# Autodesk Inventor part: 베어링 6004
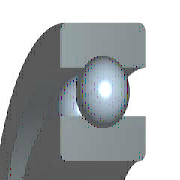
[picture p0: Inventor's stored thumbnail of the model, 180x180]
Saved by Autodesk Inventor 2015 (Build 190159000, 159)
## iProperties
IsCustomPart: 1
Created: 2012-02
Part Number: 베어링 6004
Material: 강철, 연강
Description: 깊은 그루브 볼 베어링
Document SubType Name: Modeling
Standard: KS B 2023
Designer: mduedu
Standards Organization: KS
Language: ko-KR
Size Designation: 6004 - 20 x 42 x 12
Categories: <MemberInstance><Categories><Category DisplayName="샤프트 부품" InternalName="7f7aeb1f-a693-4053-b835-cee3144e0d98" Mnemonic="SHFT"><Category DisplayName="베어링" Inter
Density: 1 g/cm^3
Appearance: 노란색
Author: mduedu
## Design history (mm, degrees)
sketch "스케치" dims "d0" = 5.72 (= -0.26 x WD + 0.26 x BD)
  geometry: L1 (3.14, 15.5)-(8.86, 15.5); L2 (6, 15.5)-(6, 12.64); L3 (6, 15.5)-(6, 18.36); L4 (3.875, 13.586)-(0, 13.586); L5 (0, 10)-(12, 10); L6 (3.875, 17.414)-(0, 17.414); L7 (0, 21)-(12, 21); L8 (12, 10)-(12, 13.586); L9 (8.125, 13.586)-(12, 13.586); L10 (8.125, 17.414)-(12, 17.414); L11 (12, 21)-(12, 17.414); L12 (-1.4, 0)-(8.4, 0) reference; L13 (0, -0.3)-(0, 5.3) reference
  constraints: 22 end point, 4 point on line, 2 collinear, 2 perpendicular, 2 symmetric about line, 1 midpoint, 1 parallel, 14 other
  dimensions: "d9" = 20 diameter of L5 L12 (= WD); "d11" = 42 diameter of L7 L12 (= BD); "d12" = 12 distance between parallel lines of L8 L13 (= KB); "d13" = 27.172 diameter of L9 L12 (= 0.326 x BD + 0.674 x WD)
revolve "본체" stored, may be unused: angle "d6" = 90 deg
revolve "볼" stored, may be unused: angle "d7" = 90 deg
pattern_circular "IDS_ARRAYBALL[SIMPL:T]" dims angle "d3" = 360 deg
body "Solid1"
fillet "모깎기1" dims "d1" = 0.6 (= KRS)
other parameters: "WD" = 20 [user parameter; used in 5 equation terms], "BD" = 42 [user parameter; used in 5 equation terms], "KB" = 12 [user parameter; used in 1 equation term], "KRS" = 0.6 [user parameter; used in 1 equation term], "d4" = 0, "d5" = 0, "d8" = 0, "d14" = 0, "d15" = 0, "BBA" = 0 [user parameter], "BC0" = 5000000 [user parameter], "BC" = 9360000 [user parameter], "BR" = 21 (= 0.5 x BD) [user parameter]
